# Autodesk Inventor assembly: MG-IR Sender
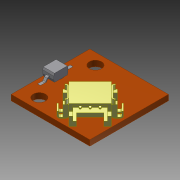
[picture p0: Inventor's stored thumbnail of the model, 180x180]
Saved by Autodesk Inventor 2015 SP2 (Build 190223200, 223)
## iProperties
Created: 2015-09
Part Number: MG-IR Sender
Document SubType Name: Assembly
Designer: rYan
Author: rYan
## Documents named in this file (4)
- E:\Tigers SVN\mechanik\2016\Inventor\Elektronik\MG-IR Sender.iam
- E:\Tigers SVN\mechanik\2016\Inventor\Elektronik\IR Board.ipt
- E:\Tigers SVN\mechanik\2016\Inventor\Kaufteile\IR LED Reverse Gullwing.ipt
- E:\Tigers SVN\mechanik\2016\Inventor\Kaufteile\DF13A-3P-1.25H.ipt
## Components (3 placed, 3 different names)
1. IR Board:1 — Einfügen:1, Winkel:1, Passend:1, Winkel:2
2. IR LED Reverse Gullwing:1 — Einfügen:1, Winkel:1
3. DF13A-3P-1.25H:1 — Passend:1, Winkel:2
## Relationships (4: Angle 2, Insert 1, Mate 1)
- Einfügen:1 [Insert]: IR Board:1 ↔ IR LED Reverse Gullwing:1
- Winkel:1 [Angle]: IR Board:1 ↔ IR LED Reverse Gullwing:1
- Passend:1 [Mate]: IR Board:1 ↔ DF13A-3P-1.25H:1
- Winkel:2 [Angle]: IR Board:1 ↔ DF13A-3P-1.25H:1
